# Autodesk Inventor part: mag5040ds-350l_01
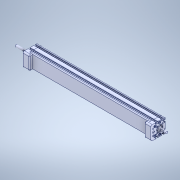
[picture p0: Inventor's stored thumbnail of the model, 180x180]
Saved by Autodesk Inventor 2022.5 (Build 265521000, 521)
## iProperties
Created: 2023-04
Part Number: mag5040ds-350l_01
Material: Generic
Document SubType Name: Modeling
Designer: ImaoCorp
Density: 1 g/cm^3
Appearance: Default
Author: ImaoCorp
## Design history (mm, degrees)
feature "mag5040ds-350l_01"
node "ソリッド1"
